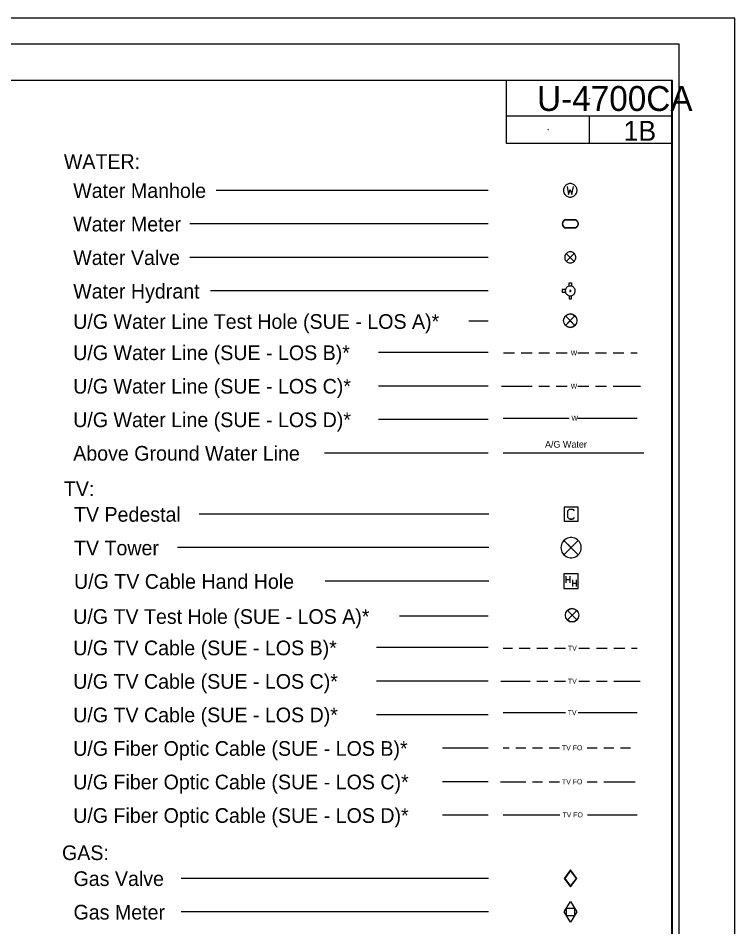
# Model space of a CAD drawing. Extents: x 811508 to 813252, y 647626 to 648754.
# Drawn here: x 812809 to 813252, y 648193 to 648754 of the extents above; entities that cross this region are included whole.
import ezdxf

# ---------------------------------------------------------------- set-up
doc = ezdxf.new("R2010")
doc.units = 0
for name, color, linetype in [('Exist Utilities TV Test Hole SUE LOS A CELL', 7, 'Continuous'), ('Exist Utilities Water Test Hole SUE LOS A CELL', 7, 'Continuous'), ('Sheet Cutting Line CELL', 7, 'Continuous'), ('Sheet Plot Border Inside CELL', 7, 'Continuous'), ('Sheet Plot Border Outside CELL', 7, 'Continuous'), ('Sheet_Plan', 7, 'Continuous'), ('Sheet_Symbology', 7, 'Continuous'), ('Sheet_Title_Block_Text', 7, 'Continuous'), ('z - Construction', 7, 'Continuous')]:
    doc.layers.add(name, color=color, linetype=linetype)

msp = doc.modelspace()

# ---------------------------------------------------------------- linework, layer by layer
at = {"layer": 'Exist Utilities TV Test Hole SUE LOS A CELL'}
for points in [[(813154.39, 648388.27), (813148.54, 648382.42), (813151.46, 648385.34), (813148.54, 648388.27), (813154.39, 648382.42)], [(813148.54, 648388.27), (813151.46, 648385.34), (813154.39, 648388.27)], [(813154.39, 648382.42), (813151.46, 648385.34), (813148.54, 648382.42)]]:
    msp.add_lwpolyline(points, dxfattribs=at)
msp.add_circle((813151.46, 648385.34), 4.14, dxfattribs=at)
for start, end in [(45, 135), (225, 315)]:
    msp.add_arc((813151.46, 648385.34), 4.14, start, end, dxfattribs=at)
at = {"layer": 'Exist Utilities Water Test Hole SUE LOS A CELL'}
for points in [[(813153.21, 648570.16), (813147.36, 648564.31), (813150.28, 648567.23), (813147.36, 648570.16), (813153.21, 648564.31)], [(813147.36, 648570.16), (813150.28, 648567.23), (813153.21, 648570.16)], [(813153.21, 648564.31), (813150.28, 648567.23), (813147.36, 648564.31)]]:
    msp.add_lwpolyline(points, dxfattribs=at)
msp.add_circle((813150.28, 648567.23), 4.14, dxfattribs=at)
for start, end in [(45, 135), (225, 315)]:
    msp.add_arc((813150.28, 648567.23), 4.14, start, end, dxfattribs=at)
at = {"layer": 'Sheet Cutting Line CELL'}
msp.add_line((813217.6, 648737.99), (811533.6, 648737.99), dxfattribs=at)
at = {"layer": 'Sheet Plot Border Inside CELL'}
msp.add_lwpolyline([(811546.6, 647660.44), (813213.1, 647660.44), (813213.1, 648715.54), (811546.6, 648715.54)], close=True, dxfattribs=at)
at = {"layer": 'Sheet Plot Border Outside CELL'}
msp.add_lwpolyline([(811533.6, 647637.99), (813217.6, 647637.99), (813217.6, 648737.99), (811533.6, 648737.99)], close=True, dxfattribs=at)
at = {"layer": 'Sheet_Plan'}
for p, q in [((813213.53, 648715.54), (811546.6, 648715.54)), ((813110.95, 648676.64), (813110.95, 648715.54)), ((813213.5, 647664.09), (813213.53, 648715.54)), ((813213.53, 648693.56), (813110.95, 648693.56)), ((813162.24, 648676.64), (813162.24, 648693.56)), ((813213.53, 648676.64), (813110.95, 648676.64))]:
    msp.add_line(p, q, dxfattribs=at)
msp.add_circle((813110.95, 648676.64), 0.0615, dxfattribs=at)
at = {"layer": 'Sheet_Symbology'}
for p, q in [((813099.59, 648647.69), (812931.53, 648647.69)), ((813147.16, 648629.65), (813153.52, 648629.65)), ((813147.16, 648629.44), (813153.52, 648629.44)), ((813099.59, 648626.99), (812915.33, 648626.99)), ((813153.48, 648624.58), (813147.16, 648624.58)), ((813153.48, 648624.37), (813147.16, 648624.37)), ((813099.59, 648606.29), (812915.33, 648606.29)), ((813099.59, 648585.59), (812928.01, 648585.59)), ((813099.59, 648566.87), (813087.64, 648566.87)), ((813099.59, 648547.57), (813031.92, 648547.57)), ((813109.09, 648547.35), (813115.81, 648547.35)), ((813119.95, 648547.35), (813126.68, 648547.35)), ((813130.82, 648547.35), (813137.55, 648547.35)), ((813141.69, 648547.35), (813148.42, 648547.35)), ((813155.04, 648547.35), (813161.77, 648547.35)), ((813165.91, 648547.35), (813172.63, 648547.35)), ((813176.77, 648547.35), (813183.5, 648547.35)), ((813187.64, 648547.35), (813191.72, 648547.35)), ((813099.59, 648526.87), (813031.92, 648526.87)), ((813107.91, 648526.87), (813126.68, 648526.87)), ((813130.82, 648526.87), (813137.55, 648526.87)), ((813141.69, 648526.87), (813148.42, 648526.87)), ((813155.04, 648526.87), (813161.77, 648526.87)), ((813165.91, 648526.87), (813172.63, 648526.87)), ((813176.77, 648526.87), (813193.65, 648526.87)), ((813099.59, 648506.17), (813031.92, 648506.17)), ((813108.92, 648507.08), (813149.59, 648507.08)), ((813154.77, 648507.08), (813191.72, 648507.08)), ((813099.59, 648485.47), (812998.46, 648485.47)), ((813108.92, 648485.7), (813195.87, 648485.7)), ((813100.09, 648447.76), (812921.12, 648447.76)), ((813150.16, 648444.71), (813151.5, 648444.71)), ((813100.09, 648427.06), (812907.75, 648427.06)), ((813147.64, 648409.49), (813147.64, 648405.32)), ((813150.02, 648409.49), (813150.02, 648405.32)), ((813100.09, 648406.36), (812998.96, 648406.36)), ((813147.64, 648407.36), (813150.02, 648407.36)), ((813151.62, 648407.22), (813151.62, 648403.05)), ((813151.62, 648405.09), (813154.01, 648405.09)), ((813154.01, 648407.22), (813154.01, 648403.05)), ((813099.59, 648384.69), (813044.88, 648384.69)), ((813099.59, 648365.32), (813030.57, 648365.32)), ((813108.92, 648364.99), (813114.69, 648364.99)), ((813118.83, 648364.99), (813125.56, 648364.99)), ((813129.7, 648364.99), (813136.42, 648364.99)), ((813140.56, 648364.99), (813147.29, 648364.99)), ((813155.57, 648364.99), (813162.3, 648364.99)), ((813166.44, 648364.99), (813173.16, 648364.99)), ((813177.3, 648364.99), (813184.03, 648364.99)), ((813188.17, 648364.99), (813191.72, 648364.99)), ((813099.59, 648344.62), (813030.57, 648344.62)), ((813107.49, 648344.62), (813125.56, 648344.62)), ((813129.7, 648344.62), (813136.42, 648344.62)), ((813140.56, 648344.62), (813147.29, 648344.62)), ((813155.57, 648344.62), (813162.3, 648344.62)), ((813166.44, 648344.62), (813173.16, 648344.62)), ((813177.3, 648344.62), (813193.46, 648344.62)), ((813108.92, 648325.18), (813147.39, 648325.18)), ((813155.16, 648325.18), (813191.72, 648325.18)), ((813099.59, 648323.92), (813030.57, 648323.92)), ((813099.59, 648303.22), (813071.4, 648303.22)), ((813108.92, 648303.47), (813112.54, 648303.47)), ((813116.68, 648303.47), (813122.89, 648303.47)), ((813127.03, 648303.47), (813133.24, 648303.47)), ((813137.38, 648303.47), (813143.59, 648303.47)), ((813160.67, 648303.47), (813166.88, 648303.47)), ((813171.02, 648303.47), (813177.23, 648303.47)), ((813181.37, 648303.47), (813187.58, 648303.47)), ((813099.59, 648282.52), (813071.4, 648282.52)), ((813107.22, 648282.52), (813122.89, 648282.52)), ((813127.03, 648282.52), (813133.24, 648282.52)), ((813137.38, 648282.52), (813143.59, 648282.52)), ((813160.67, 648282.52), (813166.88, 648282.52)), ((813171.02, 648282.52), (813190.4, 648282.52)), ((813099.59, 648261.82), (813071.4, 648261.82)), ((813108.92, 648262.07), (813143.89, 648262.07)), ((813160.96, 648262.07), (813191.72, 648262.07)), ((813150.53, 648227.72), (813146.89, 648222.84)), ((813154.17, 648222.84), (813150.53, 648227.72)), ((813099.8, 648222.84), (812909.9, 648222.84)), ((813146.89, 648222.84), (813150.53, 648217.95)), ((813150.53, 648217.95), (813154.17, 648222.84)), ((813099.8, 648202.14), (812909.9, 648202.14))]:
    msp.add_line(p, q, dxfattribs=at)
for points in [[(813150.32, 648651.89), (813149.78, 648651.85), (813149.28, 648651.75), (813148.77, 648651.59), (813148.3, 648651.35), (813147.86, 648651.08), (813147.46, 648650.75), (813147.09, 648650.34), (813146.79, 648649.94), (813146.52, 648649.47), (813146.35, 648648.96), (813146.22, 648648.46), (813146.15, 648647.96), (813146.15, 648647.42), (813146.22, 648646.91), (813146.35, 648646.38), (813146.52, 648645.9), (813146.79, 648645.43), (813147.09, 648645.03), (813147.46, 648644.63), (813147.86, 648644.29), (813148.3, 648644.02), (813148.77, 648643.79), (813149.28, 648643.62), (813149.81, 648643.52), (813150.32, 648643.48), (813150.86, 648643.52), (813151.36, 648643.62), (813151.86, 648643.79), (813152.33, 648644.02), (813152.77, 648644.29), (813153.17, 648644.63), (813153.55, 648645.03), (813153.85, 648645.43), (813154.12, 648645.9), (813154.28, 648646.41), (813154.42, 648646.91), (813154.49, 648647.42), (813154.49, 648647.96), (813154.42, 648648.46), (813154.28, 648649), (813154.12, 648649.47), (813153.85, 648649.94), (813153.55, 648650.34), (813153.17, 648650.75), (813152.77, 648651.08), (813152.33, 648651.35), (813151.86, 648651.59), (813151.36, 648651.75), (813150.82, 648651.85), (813150.32, 648651.89)], [(813148.44, 648650.01), (813149.31, 648645.1), (813150.32, 648648.19), (813151.36, 648645.1), (813152.23, 648650.01)], [(813147.16, 648629.65), (813146.74, 648629.44), (813146.37, 648629.15), (813146.04, 648628.77), (813145.79, 648628.4), (813145.58, 648627.94), (813145.46, 648627.49), (813145.41, 648627.03), (813145.46, 648626.53), (813145.58, 648626.07), (813145.79, 648625.66), (813146.04, 648625.24), (813146.37, 648624.91), (813146.74, 648624.62), (813147.16, 648624.37)], [(813147.24, 648629.48), (813146.83, 648629.23), (813146.45, 648628.94), (813146.12, 648628.57), (813145.87, 648628.19), (813145.7, 648627.74), (813145.62, 648627.24), (813145.62, 648626.78), (813145.7, 648626.32), (813145.87, 648625.86), (813146.12, 648625.45), (813146.45, 648625.07), (813146.83, 648624.78), (813147.24, 648624.58)], [(813153.39, 648629.48), (813153.85, 648629.27), (813154.22, 648628.94), (813154.51, 648628.61), (813154.76, 648628.19), (813154.93, 648627.74), (813155.01, 648627.24), (813155.01, 648626.78), (813154.93, 648626.28), (813154.76, 648625.86), (813154.51, 648625.45), (813154.18, 648625.07), (813153.81, 648624.78), (813153.39, 648624.53)], [(813153.48, 648629.65), (813153.89, 648629.44), (813154.27, 648629.15), (813154.6, 648628.77), (813154.85, 648628.4), (813155.06, 648627.94), (813155.18, 648627.49), (813155.22, 648627.03), (813155.18, 648626.53), (813155.06, 648626.07), (813154.85, 648625.66), (813154.6, 648625.24), (813154.27, 648624.91), (813153.89, 648624.62), (813153.48, 648624.37)], [(813153.75, 648606.29), (813153.72, 648606.78), (813153.6, 648607.32), (813153.41, 648607.78), (813153.14, 648608.24), (813152.84, 648608.62), (813152.46, 648608.96), (813152.04, 648609.27), (813151.58, 648609.5), (813151.08, 648609.65), (813150.59, 648609.72), (813150.05, 648609.72), (813149.55, 648609.65), (813149.06, 648609.5), (813148.6, 648609.27), (813148.18, 648608.96), (813147.8, 648608.62), (813147.49, 648608.24), (813147.22, 648607.78), (813147.03, 648607.32), (813146.92, 648606.78), (813146.88, 648606.29), (813146.92, 648605.79), (813147.03, 648605.26), (813147.22, 648604.8), (813147.49, 648604.34), (813147.8, 648603.96), (813148.18, 648603.61), (813148.6, 648603.31), (813149.06, 648603.08), (813149.55, 648602.93), (813150.05, 648602.85), (813150.59, 648602.85), (813151.08, 648602.93), (813151.58, 648603.08), (813152.04, 648603.31), (813152.46, 648603.61), (813152.84, 648603.96), (813153.14, 648604.34), (813153.41, 648604.8), (813153.6, 648605.26), (813153.72, 648605.79), (813153.75, 648606.29)], [(813152.76, 648603.84), (813147.87, 648608.73), (813150.32, 648606.29), (813147.87, 648603.84), (813152.76, 648608.73)], [(813150.28, 648588.65), (813149.8, 648588.61), (813149.32, 648588.49), (813148.85, 648588.29), (813148.45, 648588.01), (813148.09, 648587.69), (813147.78, 648587.3), (813147.54, 648586.86), (813147.38, 648586.38), (813147.26, 648585.91), (813147.26, 648585.43), (813147.34, 648584.95), (813147.46, 648584.48), (813147.7, 648584.04), (813147.97, 648583.64), (813148.33, 648583.28), (813148.73, 648582.97), (813149.16, 648582.77), (813149.64, 648582.61), (813150.12, 648582.53), (813150.6, 648582.53), (813151.07, 648582.61), (813151.55, 648582.81), (813151.99, 648583.01), (813152.38, 648583.32), (813152.7, 648583.68), (813152.98, 648584.08), (813153.18, 648584.55), (813153.34, 648585.03), (813153.38, 648585.51), (813153.34, 648585.99), (813153.26, 648586.46), (813153.06, 648586.94), (813152.82, 648587.38), (813152.5, 648587.73), (813152.11, 648588.05), (813151.71, 648588.33), (813151.23, 648588.49), (813150.75, 648588.61), (813150.28, 648588.65)], [(813149.56, 648588.57), (813149.56, 648590.55), (813151.15, 648590.55), (813151.15, 648588.53)], [(813147.38, 648586.38), (813145.39, 648586.38), (813145.39, 648584.79), (813147.38, 648584.79)], [(813149.56, 648582.61), (813149.56, 648580.62), (813151.15, 648580.62), (813151.15, 648582.65)], [(813150.32, 648585.95), (813150.16, 648585.91), (813150.04, 648585.79), (813149.96, 648585.63), (813150, 648585.47), (813150.08, 648585.31), (813150.24, 648585.23), (813150.4, 648585.23), (813150.56, 648585.31), (813150.64, 648585.47), (813150.67, 648585.63), (813150.6, 648585.79), (813150.48, 648585.91), (813150.32, 648585.95)], [(813146.5, 648443.44), (813155.13, 648443.44), (813155.13, 648452.07), (813146.5, 648452.07), (813146.5, 648443.44)], [(813152.83, 648445.67), (813151.81, 648444.71), (813149.82, 648444.71), (813148.86, 648445.67), (813148.86, 648449.84), (813149.82, 648450.8), (813151.81, 648450.8), (813152.83, 648449.84)], [(813157.05, 648427.06), (813156.98, 648427.96), (813156.77, 648428.93), (813156.42, 648429.76), (813155.94, 648430.59), (813155.38, 648431.28), (813154.69, 648431.91), (813153.93, 648432.46), (813153.1, 648432.87), (813152.2, 648433.15), (813151.3, 648433.29), (813150.33, 648433.29), (813149.43, 648433.15), (813148.53, 648432.87), (813147.69, 648432.46), (813146.93, 648431.91), (813146.24, 648431.28), (813145.69, 648430.59), (813145.2, 648429.76), (813144.85, 648428.93), (813144.65, 648427.96), (813144.58, 648427.06), (813144.65, 648426.16), (813144.85, 648425.19), (813145.2, 648424.36), (813145.69, 648423.52), (813146.24, 648422.83), (813146.93, 648422.21), (813147.69, 648421.65), (813148.53, 648421.24), (813149.43, 648420.96), (813150.33, 648420.82), (813151.3, 648420.82), (813152.2, 648420.96), (813153.1, 648421.24), (813153.93, 648421.65), (813154.69, 648422.21), (813155.38, 648422.83), (813155.94, 648423.52), (813156.42, 648424.36), (813156.77, 648425.19), (813156.98, 648426.16), (813157.05, 648427.06)], [(813155.25, 648422.62), (813146.38, 648431.49), (813150.81, 648427.06), (813146.38, 648422.62), (813155.25, 648431.49)], [(813146.36, 648401.9), (813155.27, 648401.9), (813155.27, 648410.81), (813146.36, 648410.81), (813146.36, 648401.9)], [(813150.53, 648228.14), (813146.58, 648222.84), (813150.53, 648217.54), (813154.48, 648222.84), (813150.53, 648228.14)], [(813146.58, 648202.14), (813150.53, 648208.53), (813154.48, 648202.14), (813150.53, 648195.75), (813146.58, 648202.14)], [(813148.09, 648204.53), (813152.97, 648204.53), (813152.97, 648199.7), (813148.09, 648199.7), (813148.09, 648204.53)]]:
    msp.add_lwpolyline(points, dxfattribs=at)
at = {"layer": 'z - Construction'}
for p, q in [((813251.99, 648754), (811508.14, 648754)), ((813251.99, 647625.63), (813251.99, 648754))]:
    msp.add_line(p, q, dxfattribs=at)
for centre in [(813162.24, 648704.55), (813136.59, 648685.1), (813187.88, 648685.1)]:
    msp.add_circle(centre, 0.0615, dxfattribs=at)

# ---------------------------------------------------------------- texts
at = {"layer": 'Sheet_Symbology'}
for s, height, p in [('WATER:', 9.056, (812837.46, 648660.97)), ('Water Manhole', 9.056, (812843.23, 648642.99)), ('Water Meter', 9.056, (812843.23, 648622.29)), ('Water Valve', 9.056, (812843.23, 648601.59)), ('Water Hydrant', 9.056, (812843.23, 648580.89)), ('U/G Water Line Test Hole (SUE - LOS A)*', 9.056, (812843.23, 648562.17)), ('U/G Water Line (SUE - LOS B)*', 9.056, (812843.23, 648542.88)), ('W', 3.1, (813150.59, 648545.8)), ('U/G Water Line (SUE - LOS C)*', 9.056, (812843.23, 648522.18)), ('W', 3.1, (813150.59, 648525.32)), ('U/G Water Line (SUE - LOS D)*', 9.056, (812843.23, 648501.48)), ('W', 3.1, (813151.04, 648505.53)), ('A/G Water', 4.14, (813134.72, 648488.8)), ('Above Ground Water Line', 9.056, (812843.23, 648480.78)), ('TV:', 9.056, (812837.46, 648458.88)), ('TV Pedestal', 9.056, (812843.72, 648443.06)), ('TV Tower', 9.056, (812843.72, 648422.36)), ('U/G TV Cable Hand Hole', 9.056, (812843.72, 648401.66)), ('U/G TV Test Hole (SUE - LOS A)*', 9.056, (812843.23, 648380)), ('U/G TV Cable (SUE - LOS B)*', 9.056, (812843.23, 648360.62)), ('TV', 3.105, (813148.89, 648363.43)), ('U/G TV Cable (SUE - LOS C)*', 9.056, (812843.23, 648339.93)), ('TV', 3.105, (813148.89, 648343.07)), ('U/G TV Cable (SUE - LOS D)*', 9.056, (812843.23, 648319.23)), ('TV', 3.105, (813148.74, 648323.62)), ('U/G Fiber Optic Cable (SUE - LOS B)*', 9.056, (812843.23, 648298.53)), ('TV FO', 3.105, (813145.19, 648301.92)), ('U/G Fiber Optic Cable (SUE - LOS C)*', 9.056, (812843.23, 648277.83)), ('TV FO', 3.105, (813145.19, 648280.97)), ('U/G Fiber Optic Cable (SUE - LOS D)*', 9.056, (812843.23, 648257.13)), ('TV FO', 3.105, (813145.49, 648260.52)), ('GAS:', 9.056, (812836.33, 648234.15)), ('Gas Valve', 9.056, (812843.44, 648218.14)), ('Gas Meter', 9.056, (812843.44, 648197.44))]:
    msp.add_text(s, height=height, dxfattribs=at).set_placement(p)
at = {"layer": 'Sheet_Title_Block_Text'}
for s, height, p in [('U-4700CA', 15.387, (813129.81, 648696.71)), ('1B', 12.31, (813183.25, 648678.27))]:
    msp.add_text(s, height=height, dxfattribs=at).set_placement(p)

doc.saveas('drawing.dxf')
